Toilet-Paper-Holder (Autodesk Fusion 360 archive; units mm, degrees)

design "Toilet-Paper-Holder" references "Base"
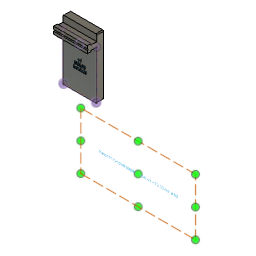
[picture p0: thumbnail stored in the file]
parameter "height" = 70
parameter "width" = 39.5 (= "hole_diameter + ( hole_padding_side * 2 )")
parameter "base_plate_width" = 8
parameter "hole_diameter" = 19.5
parameter "hole_dept" = 3
parameter "hole_padding_top" = 10
parameter "screw_hole_diameter" = 4
parameter "screw_head_hole_diameter" = 8
parameter "screw_head_hole_dept" = 3
parameter "hole_padding_side" = 10 (= "hole_padding_top")
component_insert "Component Insert"
sketch "Sketch1" plane through (0, 55.6118, 0) normal (0, 1, 0) x axis (-1, 0, 0)
  line L1 (0, 52.4859) -> (0, 47.1259)
  line L2 (-40, 52.4859) -> (0, 52.4859)
  line L3 (-40, 47.1259) -> (-40, 52.4859)
  line L4 (0, 47.1259) -> (-40, 47.1259)
  line L5 (-40, 60) -> (0, 60)
  line L6 (-39.75, 60) -> (-20, 60)
  line L7 (-0.25, 60) -> (-39.75, 60)
  line L8 (-0.25, -10) -> (-0.25, 60)
  line L9 (-39.75, -10) -> (-0.25, -10)
  line L10 (-39.75, 60) -> (-39.75, -10)
  line L11 (-20, 60) -> (-20, -10)
  line L12 (-20, 50) -> (-20, 60)
  line L13 (-20, 30.5) -> (-20, 50)
  circle C1 centre (-20, 40.25) radius 9.75
  circle C2 centre (-20, 40.25) radius 2
  circle C3 centre (-20, 40.25) radius 4
  point P8 (-20, 60)
  point P13 (-20, -10)
  point P16 (-20, 40.25)
  point P14 (-20, 50)
  point P9 (-39.75, 60)
  point P10 (-0.25, 60)
  point P12 (-39.75, -10)
  point P15 (-20, 30.5)
  midpoint L5 P8
  parallel L5 L6
  horizontal L7
  vertical L8
  horizontal L9
  vertical L10
  midpoint L9 P13
  perpendicular L2 L12
  perpendicular L4 L13
  midpoint L13 P16
  coincident P14 C1
  concentric C1 C2
  concentric C1 C3
  dimension "d3" distance P8 P9 = 19.75 (= "width / 2")
  dimension "d4" distance P9 P10 = 39.5 (= "width")
  dimension "d5" distance P9 P12 = 70 (= "height")
  dimension "d10" distance P8 P14 = 10 (= "hole_padding_top")
  dimension "d11" distance P14 P15 = 19.5 (= "hole_diameter")
  dimension "d15" diameter C2 = 4 (= "screw_hole_diameter")
  dimension "d16" diameter C3 = 8 (= "screw_head_hole_diameter")
extrude "Extrude1" new body sketch "Sketch1" profile of L1 L2 L3 L4 L5 L6 L7 L8 L9 L10 L12 L13 C1 C2 C3 along normal blind 8 (= "base_plate_width")
sketch "Sketch2" plane through (0, 63.6118, 0) normal (0, 1, 0) x axis (-1, 0, 0)
  line L1 (-0.25, -10) -> (-39.75, -10)
  line L2 (-0.25, 60) -> (-0.25, -10)
  line L3 (-39.75, 60) -> (-0.25, 60)
  line L4 (-39.75, -10) -> (-39.75, 60)
  circle C1 centre (-20, 40.25) radius 2
  circle C2 centre (-20, 40.25) radius 9.75
extrude "Extrude2" new body sketch "Sketch2" profile of C1 C2 against normal blind 3 (magnitude of "hole_dept * -1")
extrude "Extrude3" cut sketch "Sketch2" profile of C1 C2 no distance stored
extrude "Extrude4" cut sketch "Sketch1" profile of L13 C2 C3 along normal blind 3 (= "screw_head_hole_dept")
extrude "Extrude5" add of existing geometry blind 2
extrude "Extrude6" add of existing geometry to an object
fillet "Fillet1" radius 1
extrude "Extrude8" add of existing geometry to an object
extrude "Extrude9" cut of existing geometry to an object
sketch "Sketch3" plane through (0, 55.6118, 0) normal (0, -1, 0) x axis (1, 0, 0)
  line L1 (0.25, 47.1259) -> (39.75, 47.1259)
  line L2 (0.25, -9) -> (0.25, 47.1259)
  line L3 (38.75, -10) -> (1.25, -10)
  line L4 (39.75, 47.1259) -> (39.75, -9)
  curve K1
  curve K2
  curve K3
  curve K4
  arc A1 centre (1.25, -9) radius 1 clockwise from (1.25, -10) to (0.25, -9)
  arc A2 centre (38.75, -9) radius 1 clockwise from (39.75, -9) to (38.75, -10)
  circle C1 centre (20, 40.25) radius 4
  point P4 (0.25, -9)
  point P2 (39.75, 47.1259)
  coincident P4
  coincident P2
  dimension "d38" Text1-Height = 3
extrude "Extrude10" cut sketch "Sketch3" against normal blind 2
sketch "Sketch4" plane through (0, 55.6118, 0) normal (0, -1, 0) x axis (1, 0, 0)
  dimension "d42" = 3

design "Base"
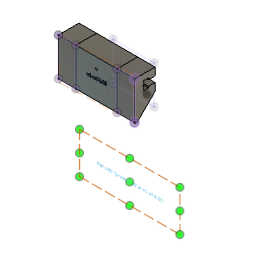
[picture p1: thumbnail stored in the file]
parameter "wall_anchor_height" = 60
parameter "wall_anchor_width" = 20
parameter "wall_anchor_angle" = 45
parameter "width_per_slot" = 40
parameter "slot_inner_width" = 8.5
parameter "slot_inner_height" = 4.5
parameter "slot_outer_width" = 5.6
parameter "slot_outer_height" = 6.5
parameter "slot_dept" = 15
parameter "print_tolerance" = 0.12
parameter "base_plate_thickness" = 16
parameter "base_plate_slot_height" = 50
parameter "wall_anchor_angle_rounded_border" = 1.5
parameter "base_plate_screw_hole_diameter" = 4
parameter "base_plate_screw_head_diameter" = 8
parameter "base_plate_screw_head_height" = 4
parameter "base_plate_screw_hole_side_distance" = 7
parameter "slot_screw_head_width" = 4.42 (= "4.3 mm + print_tolerance")
parameter "slot_screw_thread_width" = 2.12 (= "2 mm + print_tolerance")
parameter "slot_screw_head_height" = 2.12 (= "2 mm + print_tolerance")
parameter "width" = 74
parameter "filament_hole_width" = 1.7
sketch "Side" plane through (0, 0, 0) normal (1, 0, 0) x axis (0, 1, 0)
  line L1 (39.6118, 0) -> (19.6118, 0)
  line L2 (39.6118, 60) -> (39.6118, 0)
  line L3 (19.6118, 60) -> (39.6118, 60)
  line L4 (19.6118, 0) -> (19.6118, 60)
  line L5 (39.6118, 39.6118) -> (0, 0)
  line L6 (56.0196, 0) -> (0, 0)
  point P1 (0, 0)
  point P6 (0, 0)
  point P7 (39.6118, 39.6118)
  point P2 (19.6118, 0)
  point P3 (39.6118, 0)
  point P5 (19.6118, 60)
  horizontal L1
  vertical L2
  horizontal L3
  vertical L4
  horizontal L6
  coincident P1 P6
  coincident L2 P7
  dimension "d4" distance P2 P3 = 20 (= "wall_anchor_width")
  dimension "d5" distance P2 P5 = 60 (= "wall_anchor_height")
  dimension "d6" angle L5 L6 = 45 (= "wall_anchor_angle")
extrude "Extrude1" new body sketch "Side" profile of L1 L2 L3 L4 L5 along normal blind 40 (= "width_per_slot")
sketch "Slot LeftToRight" plane through (0, 0, 0) normal (-1, 0, 0) x axis (0, -1, 0)
  line L1 (-19.6118, 60) -> (-19.6118, 19.6118)
  line L2 (-39.6118, 60) -> (-19.6118, 60)
  line L3 (-39.6118, 39.6118) -> (-39.6118, 60)
  line L4 (-19.6118, 19.6118) -> (-39.6118, 39.6118)
  line L5 (-39.6118, 52.6059) -> (-39.6118, 49.8059)
  line L6 (-39.6118, 47.0059) -> (-39.6118, 49.8059)
  line L7 (-33.1118, 52.6059) -> (-39.6118, 52.6059)
  line L8 (-28.6118, 49.8059) -> (-39.6118, 49.8059)
  line L9 (-28.6118, 54.0559) -> (-28.6118, 49.8059)
  line L10 (-33.1118, 54.0559) -> (-28.6118, 54.0559)
  line L11 (-33.1118, 52.6059) -> (-33.1118, 54.0559)
  line L12 (-28.6118, 45.5559) -> (-28.6118, 49.8059)
  line L13 (-33.1118, 45.5559) -> (-28.6118, 45.5559)
  line L14 (-33.1118, 47.0059) -> (-33.1118, 45.5559)
  line L15 (-33.1118, 47.0059) -> (-39.6118, 47.0059)
  point P6 (-39.6118, 49.8059)
  point P7 (-39.6118, 52.6059)
  point P17 (-39.6118, 47.0059)
  point P9 (-33.1118, 52.6059)
  point P16 (-33.1118, 47.0059)
  point P10 (-28.6118, 49.8059)
  point P13 (-28.6118, 49.8059)
  point P11 (-28.6118, 54.0559)
  point P14 (-28.6118, 45.5559)
  point P12 (-33.1118, 54.0559)
  point P15 (-33.1118, 45.5559)
  midpoint L3 P6
  parallel L3 L5
  parallel L3 L6
  perpendicular L3 L7
  perpendicular L6 L8
  perpendicular L8 L9
  perpendicular L9 L10
  symmetric P7 L8 P17
  symmetric P9 L8 P16
  symmetric P10 L8 P13
  symmetric L8 P11 P14
  symmetric L8 P12 P15
  dimension "d80" distance P6 P7 = 2.8 (= "slot_outer_width / 2")
  dimension "d82" distance P7 P9 = 6.5 (= "slot_outer_height")
  dimension "d84" distance P6 P10 = 11 (= "slot_outer_height + slot_inner_height")
  dimension "d85" distance P10 P11 = 4.25 (= "slot_inner_width / 2")
  dimension "d86" distance P11 P12 = 4.5 (= "slot_inner_height")
extrude "Extrude3" cut sketch "Slot LeftToRight" profile of L3 L5 L6 L7 L9 L10 L11 L12 L13 L14 L15 against normal blind 40 (magnitude of "width_per_slot * -1")
sketch "Plate" plane through (0, 39.6118, 0) normal (0, 1, 0) x axis (-1, 0, 0)
  line L1 (0, 39.6118) -> (-40, 39.6118)
  line L2 (-40, 60) -> (0, 60)
  line L3 (0, 10) -> (0, 60)
  line L4 (-40, 10) -> (-40, 60)
  line L5 (-40, 10) -> (0, 10)
  line L6 (-40, 47.0059) -> (0, 47.0059)
  line L7 (-40, 52.6059) -> (-40, 60)
  line L8 (0, 60) -> (0, 52.6059)
  line L9 (0, 52.6059) -> (-40, 52.6059)
  line L10 (-40, 60) -> (0, 60)
  line L11 (-40, 39.6118) -> (-40, 47.0059)
  line L12 (0, 47.0059) -> (0, 39.6118)
  point P2 (0, 60)
  point P3 (-40, 60)
  point P4 (0, 10)
  point P5 (-40, 10)
  perpendicular L1 L3
  perpendicular L1 L4
  dimension "d36" distance P2 P3 = 40 (= "width_per_slot")
  dimension "d37" distance P2 P4 = 50 (= "base_plate_slot_height")
  dimension "d39" distance P3 P5 = 50 (= "base_plate_slot_height")
extrude "Extrude6" new body sketch "Plate" profile of L1 L2 L3 L4 L5 L6 L7 L8 L9 L10 along normal blind 16 (= "base_plate_thickness") bodies "Base plate with slot"
sketch "Slot" plane through (0, 0, 0) normal (-1, 0, 0) x axis (0, -1, 0)
  line L1 (-19.6118, 60) -> (-19.6118, 19.6118)
  line L2 (-39.6118, 60) -> (-19.6118, 60)
  line L3 (-39.6118, 52.6059) -> (-39.6118, 60)
  line L4 (-33.1118, 52.6059) -> (-39.6118, 52.6059)
  line L5 (-33.1118, 54.0559) -> (-33.1118, 52.6059)
  line L6 (-28.6118, 54.0559) -> (-33.1118, 54.0559)
  line L7 (-28.6118, 45.5559) -> (-28.6118, 54.0559)
  line L8 (-33.1118, 45.5559) -> (-28.6118, 45.5559)
  line L9 (-33.1118, 47.0059) -> (-33.1118, 45.5559)
  line L10 (-39.6118, 47.0059) -> (-33.1118, 47.0059)
  line L11 (-39.6118, 39.6118) -> (-39.6118, 47.0059)
  line L12 (-19.6118, 19.6118) -> (-39.6118, 39.6118)
  line L13 (-33.1118, 52.6059) -> (-39.6118, 52.6059)
  line L14 (-33.1118, 54.0559) -> (-33.1118, 52.6059)
  line L15 (-28.6118, 54.0559) -> (-33.1118, 54.0559)
  line L16 (-28.6118, 45.5559) -> (-28.6118, 54.0559)
  line L17 (-33.1118, 45.5559) -> (-28.6118, 45.5559)
  line L18 (-33.1118, 47.0059) -> (-33.1118, 45.5559)
  line L19 (-39.6118, 47.0059) -> (-33.1118, 47.0059)
  line L20 (-39.6118, 10) -> (-39.6118, 60)
  line L21 (-32.9918, 52.4859) -> (-39.6118, 52.4859)
  line L22 (-32.9918, 53.9359) -> (-32.9918, 52.4859)
  line L23 (-28.7318, 53.9359) -> (-32.9918, 53.9359)
  line L24 (-28.7318, 45.6759) -> (-28.7318, 53.9359)
  line L25 (-32.9918, 45.6759) -> (-28.7318, 45.6759)
  line L26 (-32.9918, 47.1259) -> (-32.9918, 45.6759)
  line L27 (-39.6118, 47.1259) -> (-32.9918, 47.1259)
  line L28 (-33.1118, 52.6059) -> (-39.6118, 52.6059)
  line L29 (-33.1118, 52.6059) -> (-33.1118, 54.0559)
  line L30 (-28.6118, 54.0559) -> (-33.1118, 54.0559)
  line L31 (-28.6118, 45.5559) -> (-28.6118, 54.0559)
  line L32 (-33.1118, 45.5559) -> (-28.6118, 45.5559)
  line L33 (-33.1118, 47.0059) -> (-33.1118, 45.5559)
  line L34 (-39.6118, 47.0059) -> (-33.1118, 47.0059)
  line L35 (-39.6118, 47.0059) -> (-39.6118, 52.6059)
  line L36 (-49.1118, 52.6059) -> (-55.6118, 52.6059)
  line L37 (-49.1118, 52.6059) -> (-49.1118, 54.0559)
  line L38 (-44.6118, 54.0559) -> (-49.1118, 54.0559)
  line L39 (-44.6118, 45.5559) -> (-44.6118, 54.0559)
  line L40 (-49.1118, 45.5559) -> (-44.6118, 45.5559)
  line L41 (-49.1118, 47.0059) -> (-49.1118, 45.5559)
  line L42 (-55.6118, 47.0059) -> (-49.1118, 47.0059)
  line L43 (-55.6118, 47.0059) -> (-55.6118, 52.6059)
  point P15 (-39.6118, 52.6059)
  point P33 (-39.6118, 52.6059)
  point P16 (-33.1118, 52.6059)
  point P34 (-33.1118, 52.6059)
  point P17 (-33.1118, 54.0559)
  point P35 (-33.1118, 54.0559)
  point P36 (-33.1118, 52.6059)
  point P18 (-28.6118, 54.0559)
  point P37 (-28.6118, 54.0559)
  point P19 (-28.6118, 45.5559)
  point P38 (-28.6118, 45.5559)
  point P10 (-28.6118, 45.5559)
  point P39 (-28.6118, 45.5559)
  point P11 (-33.1118, 45.5559)
  point P40 (-33.1118, 45.5559)
  point P41 (-33.1118, 45.5559)
  point P12 (-33.1118, 47.0059)
  point P42 (-33.1118, 47.0059)
  point P21 (-33.1118, 47.0059)
  point P43 (-33.1118, 47.0059)
  point P22 (-39.6118, 47.0059)
  point P44 (-39.6118, 47.0059)
  point P45 (-39.6118, 52.6059)
  point P46 (-39.6118, 47.0059)
  coincident P15 P33
  coincident P16 P34
  coincident P17 P35
  coincident P16 P36
  coincident P18 P37
  coincident P19 P38
  coincident P10 P39
  coincident P11 P40
  coincident P11 P41
  coincident P12 P42
  coincident P21 P43
  coincident P22 P44
  coincident P15 P45
  coincident P22 P46
  dimension "d91" = 0.12 (= "print_tolerance")
  dimension "d96" R-Pattern1-uDistance = -16 (= "base_plate_thickness * -1")
  dimension "d97" R-Pattern1-vDistance = 0
extrude "Extrude7" add sketch "Slot" profile of L20 L24 L23 L27 L22 L25 L26 L21 against normal blind 40 (magnitude of "width_per_slot * -1")
extrude "Extrude8" cut sketch "Slot" profile of L36 L37 L38 L39 L40 L41 L42 L43 no distance stored
sketch "Sketch3" plane through (0, 0, 0) normal (-1, 0, 0) x axis (0, -1, 0)
  line L1 (-32.9918, 47.1259) -> (-39.6118, 47.1259)
  line L2 (-32.9918, 45.6759) -> (-32.9918, 47.1259)
  line L3 (-28.7318, 45.6759) -> (-32.9918, 45.6759)
  line L4 (-28.7318, 53.9359) -> (-28.7318, 45.6759)
  line L5 (-32.9918, 53.9359) -> (-28.7318, 53.9359)
  line L6 (-32.9918, 52.4859) -> (-32.9918, 53.9359)
  line L7 (-39.6118, 52.4859) -> (-32.9918, 52.4859)
  line L8 (-44.6118, 45.5559) -> (-44.6118, 54.0559)
  line L9 (-32.9918, 52.4859) -> (-39.6118, 52.4859)
  line L10 (-32.9918, 53.9359) -> (-32.9918, 52.4859)
  line L11 (-28.7318, 53.9359) -> (-32.9918, 53.9359)
  line L12 (-28.7318, 45.6759) -> (-28.7318, 53.9359)
  line L13 (-32.9918, 45.6759) -> (-28.7318, 45.6759)
  line L14 (-32.9918, 47.1259) -> (-32.9918, 45.6759)
  line L15 (-39.6118, 47.1259) -> (-32.9918, 47.1259)
  line L16 (-39.6118, 47.1259) -> (-39.6118, 52.4859)
  line L17 (-55.6118, 52.4859) -> (-48.9918, 52.4859)
  line L18 (-48.9918, 52.4859) -> (-48.9918, 53.9359)
  line L19 (-48.9918, 53.9359) -> (-44.7318, 53.9359)
  line L20 (-44.7318, 45.6759) -> (-44.7318, 53.9359)
  line L21 (-48.9918, 45.6759) -> (-44.7318, 45.6759)
  line L22 (-48.9918, 47.1259) -> (-48.9918, 45.6759)
  line L23 (-55.6118, 47.1259) -> (-48.9918, 47.1259)
  line L24 (-55.6118, 47.1259) -> (-55.6118, 52.4859)
  line L25 (-55.6118, 47.0059) -> (-49.1118, 47.0059)
  line L26 (-55.6118, 10) -> (-55.6118, 47.0059)
  line L27 (-39.6118, 10) -> (-55.6118, 10)
  line L28 (-39.6118, 47.1259) -> (-39.6118, 10)
  line L29 (-39.6118, 60) -> (-39.6118, 52.4859)
  line L30 (-55.6118, 60) -> (-39.6118, 60)
  line L31 (-55.6118, 52.6059) -> (-55.6118, 60)
  line L32 (-49.1118, 52.6059) -> (-55.6118, 52.6059)
  line L33 (-49.1118, 54.0559) -> (-49.1118, 52.6059)
  line L34 (-44.6118, 54.0559) -> (-49.1118, 54.0559)
  line L35 (-49.1118, 45.5559) -> (-44.6118, 45.5559)
  line L36 (-49.1118, 47.0059) -> (-49.1118, 45.5559)
  point P9 (-39.6118, 52.4859)
  point P20 (-39.6118, 52.4859)
  point P19 (-39.6118, 47.1259)
  point P21 (-39.6118, 47.1259)
  coincident P9 P20
  coincident P19 P21
  dimension "d105" R-Pattern1-vDistance = 0
extrude "Extrude3" new body sketch "Sketch3" profile of L17 L18 L19 L20 L21 L22 L23 L24 against normal blind 40 (magnitude of "width_per_slot * -1")
sketch "Screw hole" plane through (0, 28.6118, 0) normal (0, 1, 0) x axis (-1, 0, 0)
  line L1 (0, 54.0559) -> (0, 45.5559)
  line L2 (-40, 54.0559) -> (0, 54.0559)
  line L3 (-40, 45.5559) -> (-40, 54.0559)
  line L4 (0, 45.5559) -> (-40, 45.5559)
  line L5 (0, 45.5559) -> (-40, 54.0559)
  line L6 (-40, 45.5559) -> (0, 54.0559)
  circle C1 centre (-20, 49.8059) radius 2.21
  circle C2 centre (-20, 49.8059) radius 1.06
  point P4 (-40, 54.0559)
  point P6 (-40, 54.0559)
  point P2 (0, 45.5559)
  point P7 (0, 45.5559)
  point P3 (0, 54.0559)
  point P8 (0, 54.0559)
  point P5 (-40, 45.5559)
  point P9 (-40, 45.5559)
  point P10 (-20, 49.8059)
  coincident P4 P6
  coincident P2 P7
  coincident P3 P8
  coincident P5 P9
  midpoint L5 P10
  concentric C1 C2
  dimension "d119" diameter C1 = 4.42 (= "slot_screw_head_width")
  dimension "d120" diameter C2 = 2.12 (= "slot_screw_thread_width")
extrude "Extrude4" cut sketch "Screw hole" profile of C2 against normal blind 2000
extrude "Extrude5" cut sketch "Screw hole" profile of C1 C2 no distance stored
fillet "Fillet1" radius 1.5 (= "wall_anchor_angle_rounded_border")
work_plane "WorkPlane1" sketch "Slot LeftToRight" AlongDistance -20 (= "-width_per_slot / 2")
sketch "Screw head" plane through (20, 0, 0) normal (-1, 0, 0) x axis (0, -1, 0)
  line L1 (-28.6118, 52.0159) -> (-28.6118, 47.5959)
  line L2 (-26.4918, 52.0159) -> (-26.4918, 47.5959)
  line L3 (-26.4918, 48.7459) -> (-26.4918, 50.8659)
  line L4 (-26.4918, 50.8659) -> (-28.6118, 52.0159)
  line L5 (-26.4918, 52.0159) -> (-28.6118, 52.0159)
  point P3 (-28.6118, 52.0159)
  point P8 (-28.6118, 52.0159)
  point P6 (-26.4918, 50.8659)
  point P9 (-26.4918, 50.8659)
  point P10 (-28.6118, 52.0159)
  point P5 (-26.4918, 52.0159)
  point P11 (-26.4918, 52.0159)
  coincident P3 P8
  coincident P6 P9
  coincident P3 P10
  coincident P5 P11
revolve "Revolve1" sketch "Screw head" AlongAngle 360
sketch "Plate" plane through (0, 39.6118, 0) normal (0, 1, 0) x axis (-1, 0, 0)
  line L1 (0, 39.6118) -> (-40, 39.6118)
  line L2 (-40, 60) -> (0, 60)
  line L3 (0, 10) -> (0, 60)
  line L4 (-40, 10) -> (-40, 60)
  line L5 (-40, 10) -> (0, 10)
  line L6 (-40, 47.0059) -> (0, 47.0059)
  line L7 (-40, 39.6118) -> (-40, 47.0059)
  line L8 (0, 47.0059) -> (0, 39.6118)
  line L9 (0, 52.6059) -> (-40, 52.6059)
  line L10 (-40, 60) -> (0, 60)
  line L11 (0, 60) -> (0, 52.6059)
  line L12 (-40, 52.6059) -> (-40, 60)
  point P2 (0, 60)
  point P3 (-40, 60)
  point P4 (0, 10)
  point P5 (-40, 10)
  perpendicular L1 L3
  perpendicular L1 L4
  dimension "d36_1" distance P2 P3 = 40 (= "width_per_slot")
  dimension "d37_1" distance P2 P4 = 50 (= "base_plate_slot_height")
  dimension "d39_1" distance P3 P5 = 50 (= "base_plate_slot_height")
extrude "Extrude6" new body sketch "Plate" profile of L1 L2 L3 L4 L5 L6 L7 L8 L9 L10 along normal blind 16 (= "base_plate_thickness") named "d89_1" bodies "Base plate with slot"
sketch "Slot" plane through (0, 0, 0) normal (-1, 0, 0) x axis (0, -1, 0)
  line L1 (-19.6118, 60) -> (-19.6118, 23.2332)
  line L2 (-39.6118, 60) -> (-19.6118, 60)
  line L3 (-39.6118, 52.6059) -> (-39.6118, 60)
  line L4 (-33.1118, 52.6059) -> (-39.6118, 52.6059)
  line L5 (-33.1118, 54.0559) -> (-33.1118, 52.6059)
  line L6 (-28.6118, 54.0559) -> (-33.1118, 54.0559)
  line L7 (-28.6118, 45.5559) -> (-28.6118, 54.0559)
  line L8 (-33.1118, 45.5559) -> (-28.6118, 45.5559)
  line L9 (-33.1118, 47.0059) -> (-33.1118, 45.5559)
  line L10 (-39.6118, 47.0059) -> (-33.1118, 47.0059)
  line L11 (-39.6118, 39.6118) -> (-39.6118, 47.0059)
  line L12 (-22.1725, 22.1725) -> (-39.6118, 39.6118)
  line L13 (-33.1118, 52.6059) -> (-39.6118, 52.6059)
  line L14 (-33.1118, 54.0559) -> (-33.1118, 52.6059)
  line L15 (-28.6118, 54.0559) -> (-33.1118, 54.0559)
  line L16 (-28.6118, 45.5559) -> (-28.6118, 54.0559)
  line L17 (-33.1118, 45.5559) -> (-28.6118, 45.5559)
  line L18 (-33.1118, 47.0059) -> (-33.1118, 45.5559)
  line L19 (-39.6118, 47.0059) -> (-33.1118, 47.0059)
  line L20 (-39.6118, 10) -> (-39.6118, 60)
  line L21 (-32.9918, 52.4859) -> (-39.6118, 52.4859)
  line L22 (-32.9918, 53.9359) -> (-32.9918, 52.4859)
  line L23 (-28.7318, 53.9359) -> (-32.9918, 53.9359)
  line L24 (-28.7318, 45.6759) -> (-28.7318, 53.9359)
  line L25 (-32.9918, 45.6759) -> (-28.7318, 45.6759)
  line L26 (-32.9918, 47.1259) -> (-32.9918, 45.6759)
  line L27 (-39.6118, 47.1259) -> (-32.9918, 47.1259)
  line L28 (-33.1118, 52.6059) -> (-39.6118, 52.6059)
  line L29 (-33.1118, 52.6059) -> (-33.1118, 54.0559)
  line L30 (-28.6118, 54.0559) -> (-33.1118, 54.0559)
  line L31 (-28.6118, 45.5559) -> (-28.6118, 54.0559)
  line L32 (-33.1118, 45.5559) -> (-28.6118, 45.5559)
  line L33 (-33.1118, 47.0059) -> (-33.1118, 45.5559)
  line L34 (-39.6118, 47.0059) -> (-33.1118, 47.0059)
  line L35 (-39.6118, 47.0059) -> (-39.6118, 52.6059)
  line L36 (-49.1118, 52.6059) -> (-55.6118, 52.6059)
  line L37 (-49.1118, 52.6059) -> (-49.1118, 54.0559)
  line L38 (-44.6118, 54.0559) -> (-49.1118, 54.0559)
  line L39 (-44.6118, 45.5559) -> (-44.6118, 54.0559)
  line L40 (-49.1118, 45.5559) -> (-44.6118, 45.5559)
  line L41 (-49.1118, 47.0059) -> (-49.1118, 45.5559)
  line L42 (-55.6118, 47.0059) -> (-49.1118, 47.0059)
  line L43 (-55.6118, 47.0059) -> (-55.6118, 52.6059)
  arc A1 centre (-21.1118, 23.2332) radius 1.5 clockwise from (-19.6118, 23.2332) to (-22.1725, 22.1725)
  point P15 (-39.6118, 52.6059)
  point P33 (-39.6118, 52.6059)
  point P16 (-33.1118, 52.6059)
  point P34 (-33.1118, 52.6059)
  point P17 (-33.1118, 54.0559)
  point P35 (-33.1118, 54.0559)
  point P36 (-33.1118, 52.6059)
  point P18 (-28.6118, 54.0559)
  point P37 (-28.6118, 54.0559)
  point P19 (-28.6118, 45.5559)
  point P38 (-28.6118, 45.5559)
  point P10 (-28.6118, 45.5559)
  point P39 (-28.6118, 45.5559)
  point P11 (-33.1118, 45.5559)
  point P40 (-33.1118, 45.5559)
  point P41 (-33.1118, 45.5559)
  point P12 (-33.1118, 47.0059)
  point P42 (-33.1118, 47.0059)
  point P21 (-33.1118, 47.0059)
  point P43 (-33.1118, 47.0059)
  point P22 (-39.6118, 47.0059)
  point P44 (-39.6118, 47.0059)
  point P45 (-39.6118, 52.6059)
  point P46 (-39.6118, 47.0059)
  coincident P15 P33
  coincident P16 P34
  coincident P17 P35
  coincident P16 P36
  coincident P18 P37
  coincident P19 P38
  coincident P10 P39
  coincident P11 P40
  coincident P11 P41
  coincident P12 P42
  coincident P21 P43
  coincident P22 P44
  coincident P15 P45
  coincident P22 P46
  dimension "d91_1" = 0.12 (= "print_tolerance")
  dimension "d96_1" R-Pattern1-uDistance = -16 (= "base_plate_thickness * -1")
  dimension "d97_1" R-Pattern1-vDistance = 0
extrude "Extrude8" cut sketch "Slot" profile of L36 L37 L38 L39 L40 L41 L42 L43 no distance stored
sketch "Screw" plane through (0, 55.6118, 0) normal (0, 1, 0) x axis (-1, 0, 0)
  line L1 (-40, 47.0059) -> (0, 47.0059)
  line L2 (-40, 10) -> (-40, 47.0059)
  line L3 (0, 10) -> (-40, 10)
  line L4 (0, 47.0059) -> (0, 10)
  line L5 (-33, 17) -> (-33, 40.0059)
  line L6 (-7, 17) -> (-33, 17)
  line L7 (-7, 40.0059) -> (-7, 17)
  line L8 (-33, 40.0059) -> (-7, 40.0059)
  circle C1 centre (-33, 17) radius 4
  circle C2 centre (-33, 17) radius 2
  point P7 (-33, 17)
  point P10 (-33, 17)
  coincident P7 P10
  concentric C1 C2
  dimension "d127" = -7 (= "base_plate_screw_hole_side_distance * -1")
  dimension "d128" diameter C1 = 8
  dimension "d129" diameter C2 = 4
rectangular_pattern "R-Pattern2" countU 1 (= "floor(( width / mm ) / ( width_per_slot / cm * 10 ))") uSpaceDistance 40 (= "width_per_slot") vSpaceDistance 0
work_plane "WorkPlane2"
extrude "Extrude12" new body of existing geometry no distance stored
mirror "Mirror3" mirrorStitchTolerance 0.1
sketch "filename" plane through (0, 19.6118, 0) normal (0, -1, 0) x axis (1, 0, 0)
  dimension "d216" = 3
sketch "Sketch14" plane through (0, 19.6118, 0) normal (0, -1, 0) x axis (1, 0, 0)
  line L1 (57, 60) -> (57, 23.2332)
  line L2 (40, 23.2332) -> (40, 60)
  line L3 (57, 23.2332) -> (40, 23.2332)
  line L4 (57, 60) -> (57, 23.2332)
  line L5 (40, 60) -> (57, 60)
  line L6 (0, 60) -> (0, 23.2332)
  line L7 (-17, 60) -> (0, 60)
  line L8 (-17, 23.2332) -> (-17, 60)
  line L9 (0, 23.2332) -> (-17, 23.2332)
  curve K1
  curve K2
  curve K3
  curve K4
  point P4 (57, 23.2332)
  point P2 (-17, 60)
  coincident P4
  coincident P2
  dimension "d229" Text1-Height = 3
extrude "Extrude19" cut sketch "Sketch14" against normal blind 2
extrude "Extrude14" cut of existing geometry blind 17 (= "( width_per_slot - width ) / -2")
extrude "Extrude15" cut of existing geometry blind 17 (= "( width_per_slot - width ) / -2")
extrude "Extrude9" cut of existing geometry blind -39 (= "-width_per_slot + 1 mm")
extrude "Extrude10" add of existing geometry blind 73 (= "width - 1 mm")
sketch "Sketch7" plane through (0, 39.6118, 0) normal (0, -1, 0) x axis (1, 0, 0)
  dimension "d236" = 3
extrude "Extrude11" cut sketch "Sketch7" against normal blind 2
sketch "Sketch8" plane through (0, 39.6118, 0) normal (0, -1, 0) x axis (1, 0, 0)
  line L1 (31.0624, 30.0752) -> (30.825, 30.0752)
  line L2 (31.0624, 27.063) -> (31.0624, 30.0752)
  line L3 (30.6941, 27.063) -> (31.0624, 27.063)
  line L4 (30.6941, 29.4102) -> (30.6941, 27.063)
  curve K1 (30.3441, 29.1564) -> (30.6941, 29.4102)
  curve K2 (29.9574, 28.9661) -> (30.3441, 29.1564)
  line L5 (29.9574, 29.3222) -> (29.9574, 28.9661)
  curve K3 (30.4976, 29.6741) -> (29.9574, 29.3222)
  curve K4 (30.825, 30.0752) -> (30.4976, 29.6741)
  line L6 (34.2896, 27.063) -> (34.7295, 28.7349)
  line L7 (33.9048, 27.063) -> (34.2896, 27.063)
  line L8 (33.2398, 29.2362) -> (33.9048, 27.063)
  line L9 (33.6204, 29.2362) -> (33.2398, 29.2362)
  line L10 (33.9662, 27.9818) -> (33.6204, 29.2362)
  line L11 (34.0952, 27.5152) -> (33.9662, 27.9818)
  curve K5 (34.2077, 27.9634) -> (34.0952, 27.5152)
  line L12 (34.5535, 29.2362) -> (34.2077, 27.9634)
  line L13 (34.9321, 29.2362) -> (34.5535, 29.2362)
  line L14 (35.2575, 27.9756) -> (34.9321, 29.2362)
  line L15 (35.366, 27.5602) -> (35.2575, 27.9756)
  line L16 (35.4908, 27.9797) -> (35.366, 27.5602)
  line L17 (35.8632, 29.2362) -> (35.4908, 27.9797)
  line L18 (36.2213, 29.2362) -> (35.8632, 29.2362)
  line L19 (35.5419, 27.063) -> (36.2213, 29.2362)
  line L20 (35.1593, 27.063) -> (35.5419, 27.063)
  line L21 (34.8134, 28.3645) -> (35.1593, 27.063)
  line L22 (34.7295, 28.7349) -> (34.8134, 28.3645)
  curve K6 (44.1429, 29.2505) -> (43.9567, 29.6967)
  curve K7 (44.2104, 28.5425) -> (44.1429, 29.2505)
  curve K8 (44.102, 27.6892) -> (44.2104, 28.5425)
  curve K9 (43.7766, 27.1878) -> (44.102, 27.6892)
  curve K10 (43.2323, 27.0118) -> (43.7766, 27.1878)
  curve K11 (42.5508, 27.3228) -> (43.2323, 27.0118)
  curve K12 (42.2541, 28.5425) -> (42.5508, 27.3228)
  line L23 (33.0965, 27.9634) -> (33.0965, 28.3338)
  line L24 (31.9649, 27.9634) -> (33.0965, 27.9634)
  line L25 (31.9649, 28.3338) -> (31.9649, 27.9634)
  line L26 (33.0965, 28.3338) -> (31.9649, 28.3338)
  line L27 (28.6293, 27.063) -> (29.4519, 29.2362)
  line L28 (28.2855, 27.063) -> (28.6293, 27.063)
  line L29 (27.4587, 29.2362) -> (28.2855, 27.063)
  line L30 (27.8475, 29.2362) -> (27.4587, 29.2362)
  line L31 (28.3141, 27.9347) -> (27.8475, 29.2362)
  curve K13 (28.4533, 27.4968) -> (28.3141, 27.9347)
  curve K14 (28.5904, 27.9102) -> (28.4533, 27.4968)
  line L32 (29.0733, 29.2362) -> (28.5904, 27.9102)
  line L33 (29.4519, 29.2362) -> (29.0733, 29.2362)
  line L34 (0, 47.1259) -> (74, 47.1259)
  line L35 (0, 10) -> (0, 47.1259)
  line L36 (74, 10) -> (0, 10)
  line L37 (74, 47.1259) -> (74, 10)
  curve K15
  curve K16
  curve K17
  curve K18
  curve K19 (45.0188, 29.8992) -> (44.6934, 29.3979)
  curve K20 (45.5631, 30.0752) -> (45.0188, 29.8992)
  curve K21 (44.6934, 29.3979) -> (44.5849, 28.5425)
  curve K22 (37.8257, 28.9272) -> (38.3946, 29.7376)
  curve K23 (37.3919, 27.8876) -> (37.8257, 28.9272)
  curve K24 (37.2507, 27.063) -> (37.3919, 27.8876)
  curve K25 (37.0113, 27.9183) -> (36.8721, 27.063)
  curve K26 (37.3919, 28.8842) -> (37.0113, 27.9183)
  curve K27 (37.9219, 29.6701) -> (37.3919, 28.8842)
  curve K28 (44.8816, 27.3228) -> (45.5631, 27.0118)
  curve K29 (44.5849, 28.5425) -> (44.8816, 27.3228)
  curve K30 (45.9867, 29.977) -> (45.5631, 30.0752)
  curve K31 (46.2875, 29.6967) -> (45.9867, 29.977)
  curve K32 (46.4737, 29.2505) -> (46.2875, 29.6967)
  curve K33 (46.5413, 28.5425) -> (46.4737, 29.2505)
  curve K34 (46.4328, 27.6892) -> (46.5413, 28.5425)
  curve K35 (46.1074, 27.1878) -> (46.4328, 27.6892)
  curve K36 (45.5631, 27.0118) -> (46.1074, 27.1878)
  line L38 (40.308, 27.063) -> (40.308, 27.7812)
  line L39 (39.9396, 27.063) -> (40.308, 27.063)
  line L40 (39.9396, 27.7812) -> (39.9396, 27.063)
  line L41 (38.6381, 27.7812) -> (39.9396, 27.7812)
  line L42 (38.6381, 28.1189) -> (38.6381, 27.7812)
  line L43 (40.0072, 30.063) -> (38.6381, 28.1189)
  line L44 (40.308, 30.063) -> (40.0072, 30.063)
  line L45 (40.308, 28.1189) -> (40.308, 30.063)
  line L46 (40.7132, 28.1189) -> (40.308, 28.1189)
  line L47 (40.7132, 27.7812) -> (40.7132, 28.1189)
  line L48 (40.308, 27.7812) -> (40.7132, 27.7812)
  curve K37 (42.3626, 29.3979) -> (42.2541, 28.5425)
  curve K38 (42.6879, 29.8992) -> (42.3626, 29.3979)
  curve K39 (43.2323, 30.0752) -> (42.6879, 29.8992)
  curve K40 (43.6559, 29.977) -> (43.2323, 30.0752)
  curve K41 (43.9567, 29.6967) -> (43.6559, 29.977)
  line L49 (41.7159, 27.063) -> (41.7159, 27.4825)
  line L50 (41.2964, 27.063) -> (41.7159, 27.063)
  line L51 (41.2964, 27.4825) -> (41.2964, 27.063)
  line L52 (41.7159, 27.4825) -> (41.2964, 27.4825)
  line L53 (36.4526, 29.6701) -> (37.9219, 29.6701)
  line L54 (36.4526, 30.0241) -> (36.4526, 29.6701)
  line L55 (38.3946, 30.0241) -> (36.4526, 30.0241)
  line L56 (38.3946, 29.7376) -> (38.3946, 30.0241)
  line L57 (36.8721, 27.063) -> (37.2507, 27.063)
  dimension "d239" Text1-Height = 3
sketch "Sketch4" plane through (40, 0, 0) normal (1, 0, 0) x axis (0, 1, 0)
  line L1 (44.7318, 53.9359) -> (48.9918, 53.9359)
  line L2 (44.7318, 45.6759) -> (44.7318, 53.9359)
  line L3 (48.9918, 45.6759) -> (44.7318, 45.6759)
  line L4 (48.9918, 47.1259) -> (48.9918, 45.6759)
  line L5 (55.6118, 47.1259) -> (48.9918, 47.1259)
  line L6 (55.6118, 52.4859) -> (55.6118, 47.1259)
  line L7 (48.9918, 52.4859) -> (55.6118, 52.4859)
  line L8 (48.9918, 53.9359) -> (48.9918, 52.4859)
  circle C1 centre (44.7318, 49.8059) radius 0.85
  point P10 (44.7318, 49.8059)
  midpoint L2 P10
  dimension "d241" diameter C1 = 1.7 (= "filament_hole_width")
extrude "Extrude4" cut sketch "Sketch4" profile of L2 C1 no distance stored
sketch "Sketch15" plane through (-17, 0, 0) normal (-1, 0, 0) x axis (0, -1, 0)
  line L1 (-19.6118, 60) -> (-19.6118, 23.2332)
  line L2 (-39.6118, 60) -> (-19.6118, 60)
  line L3 (-39.6118, 52.6059) -> (-39.6118, 60)
  line L4 (-33.1118, 52.6059) -> (-39.6118, 52.6059)
  line L5 (-33.1118, 54.0559) -> (-33.1118, 52.6059)
  line L6 (-28.6118, 54.0559) -> (-33.1118, 54.0559)
  line L7 (-28.6118, 45.5559) -> (-28.6118, 54.0559)
  line L8 (-33.1118, 45.5559) -> (-28.6118, 45.5559)
  line L9 (-33.1118, 47.0059) -> (-33.1118, 45.5559)
  line L10 (-39.6118, 47.0059) -> (-33.1118, 47.0059)
  line L11 (-39.6118, 39.6118) -> (-39.6118, 47.0059)
  line L12 (-22.1725, 22.1725) -> (-39.6118, 39.6118)
  arc A1 centre (-21.1118, 23.2332) radius 1.5 clockwise from (-19.6118, 23.2332) to (-22.1725, 22.1725)
  circle C1 centre (-28.6118, 49.8059) radius 0.85
  point P16 (-28.6118, 49.8059)
  midpoint L7 P16
  dimension "d244" diameter C1 = 1.7 (= "filament_hole_width")
extrude "Extrude20" cut sketch "Sketch15" profile of L7 C1 no distance stored
sketch "Sketch9" plane through (74, 0, 0) normal (1, 0, 0) x axis (0, 1, 0)
  line L1 (49.1118, 47.0059) -> (55.6118, 47.0059)
  line L2 (49.1118, 45.5559) -> (49.1118, 47.0059)
  line L3 (44.6118, 45.5559) -> (49.1118, 45.5559)
  line L4 (44.6118, 54.0559) -> (44.6118, 45.5559)
  line L5 (49.1118, 54.0559) -> (44.6118, 54.0559)
  line L6 (49.1118, 52.6059) -> (49.1118, 54.0559)
  line L7 (55.6118, 52.6059) -> (49.1118, 52.6059)
  line L8 (55.6118, 60) -> (55.6118, 52.6059)
  line L9 (39.6118, 60) -> (55.6118, 60)
  line L10 (39.6118, 52.4859) -> (39.6118, 60)
  line L11 (32.9918, 52.4859) -> (39.6118, 52.4859)
  line L12 (32.9918, 53.9359) -> (32.9918, 52.4859)
  line L13 (28.7318, 53.9359) -> (32.9918, 53.9359)
  line L14 (28.7318, 45.6759) -> (28.7318, 53.9359)
  line L15 (32.9918, 45.6759) -> (28.7318, 45.6759)
  line L16 (32.9918, 47.1259) -> (32.9918, 45.6759)
  line L17 (39.6118, 47.1259) -> (32.9918, 47.1259)
  line L18 (39.6118, 10) -> (39.6118, 47.1259)
  line L19 (55.6118, 10) -> (39.6118, 10)
  line L20 (55.6118, 47.0059) -> (55.6118, 10)
  circle C1 centre (28.7318, 49.8059) radius 0.85
  circle C2 centre (44.6118, 49.8059) radius 0.85
  point P22 (28.7318, 49.8059)
  point P23 (44.6118, 49.8059)
  midpoint L14 P22
  midpoint L4 P23
  dimension "d247" diameter C1 = 1.7 (= "filament_hole_width")
  dimension "d250" diameter C2 = 1.7 (= "filament_hole_width")
extrude "Extrude12" cut sketch "Sketch9" profile of L4 L14 C1 C2 no distance stored
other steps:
create_component "CreateComponent1"
create_component "CreateComponent2"
create_component "CreateComponent3"
create_component "CreateComponent4"
named bodies: "Wall anchor part", "Base plate with slot"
